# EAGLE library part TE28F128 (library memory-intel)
FLASH Strata-Flash 128 Mb Memory
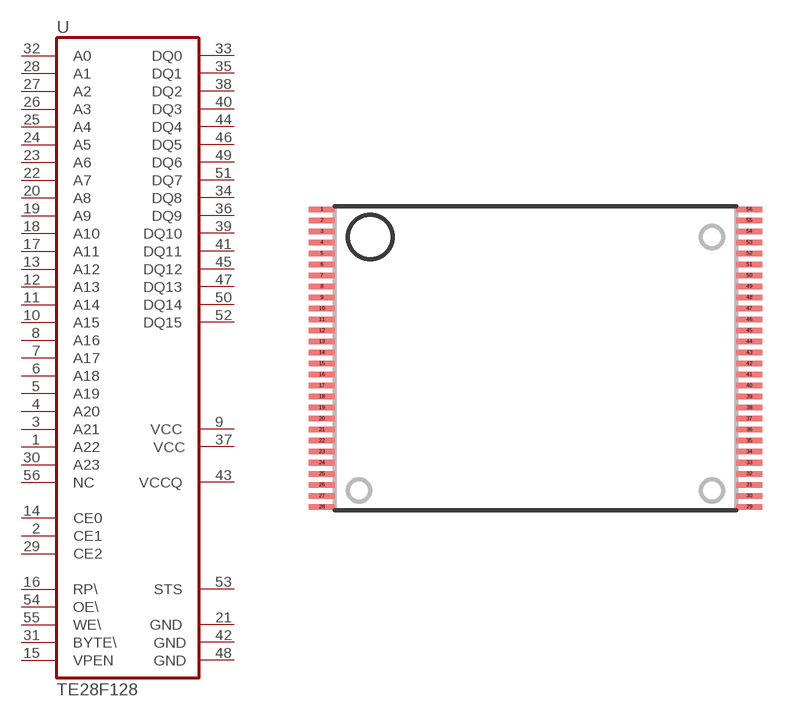
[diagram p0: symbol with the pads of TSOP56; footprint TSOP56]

Designator prefix U

## TE28F128  [TSOP56]
1  A22  in
2  CE1  in
3  A21  in
4  A20  in
5  A19  in
6  A18  in
7  A17  in
8  A16  in
9  VCC  pwr
10  A15  in
11  A14  in
12  A13  in
13  A12  in
14  CE0  in
15  VPEN  in
16  RP\  in
17  A11  in
18  A10  in
19  A9  in
20  A8  in
21  GND  pwr
22  A7  in
23  A6  in
24  A5  in
25  A4  in
26  A3  in
27  A2  in
28  A1  in
29  CE2  in
30  A23  in
31  BYTE\  in
32  A0  in
33  DQ0
34  DQ8
35  DQ1
36  DQ9
37  VCC2  pwr
38  DQ2
39  DQ10
40  DQ3
41  DQ11
42  GND2  pwr
43  VCCQ  pwr
44  DQ4
45  DQ12
46  DQ5
47  DQ13
48  GND3  pwr
49  DQ6
50  DQ14
51  DQ7
52  DQ15
53  STS  out
54  OE\  in
55  WE\  in
56  NC

## Footprint TSOP56 (pad centres in mm)
Thin Small Outline Package
smd 1.2 x 0.25: 1 -9.7,6.75; 2 -9.7,6.25; 3 -9.7,5.75; 4 -9.7,5.25; 5 -9.7,4.75; 6 -9.7,4.25; 7 -9.7,3.75; 8 -9.7,3.25; 9 -9.7,2.75; 10 -9.7,2.25; 11 -9.7,1.75; 12 -9.7,1.25; 13 -9.7,0.75; 14 -9.7,0.25; 15 -9.7,-0.25; 16 -9.7,-0.75; 17 -9.7,-1.25; 18 -9.7,-1.75; 19 -9.7,-2.25; 20 -9.7,-2.75; 21 -9.7,-3.25; 22 -9.7,-3.75; 23 -9.7,-4.25; 24 -9.7,-4.75; 25 -9.7,-5.25; 26 -9.7,-5.75; 27 -9.7,-6.25; 28 -9.7,-6.75; 29 9.7,-6.75; 30 9.7,-6.25; 31 9.7,-5.75; 32 9.7,-5.25; 33 9.7,-4.75; 34 9.7,-4.25; 35 9.7,-3.75; 36 9.7,-3.25; 37 9.7,-2.75; 38 9.7,-2.25; 39 9.7,-1.75; 40 9.7,-1.25; 41 9.7,-0.75; 42 9.7,-0.25; 43 9.7,0.25; 44 9.7,0.75; 45 9.7,1.25; 46 9.7,1.75; 47 9.7,2.25; 48 9.7,2.75; 49 9.7,3.25; 50 9.7,3.75; 51 9.7,4.25; 52 9.7,4.75; 53 9.7,5.25; 54 9.7,5.75; 55 9.7,6.25; 56 9.7,6.75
